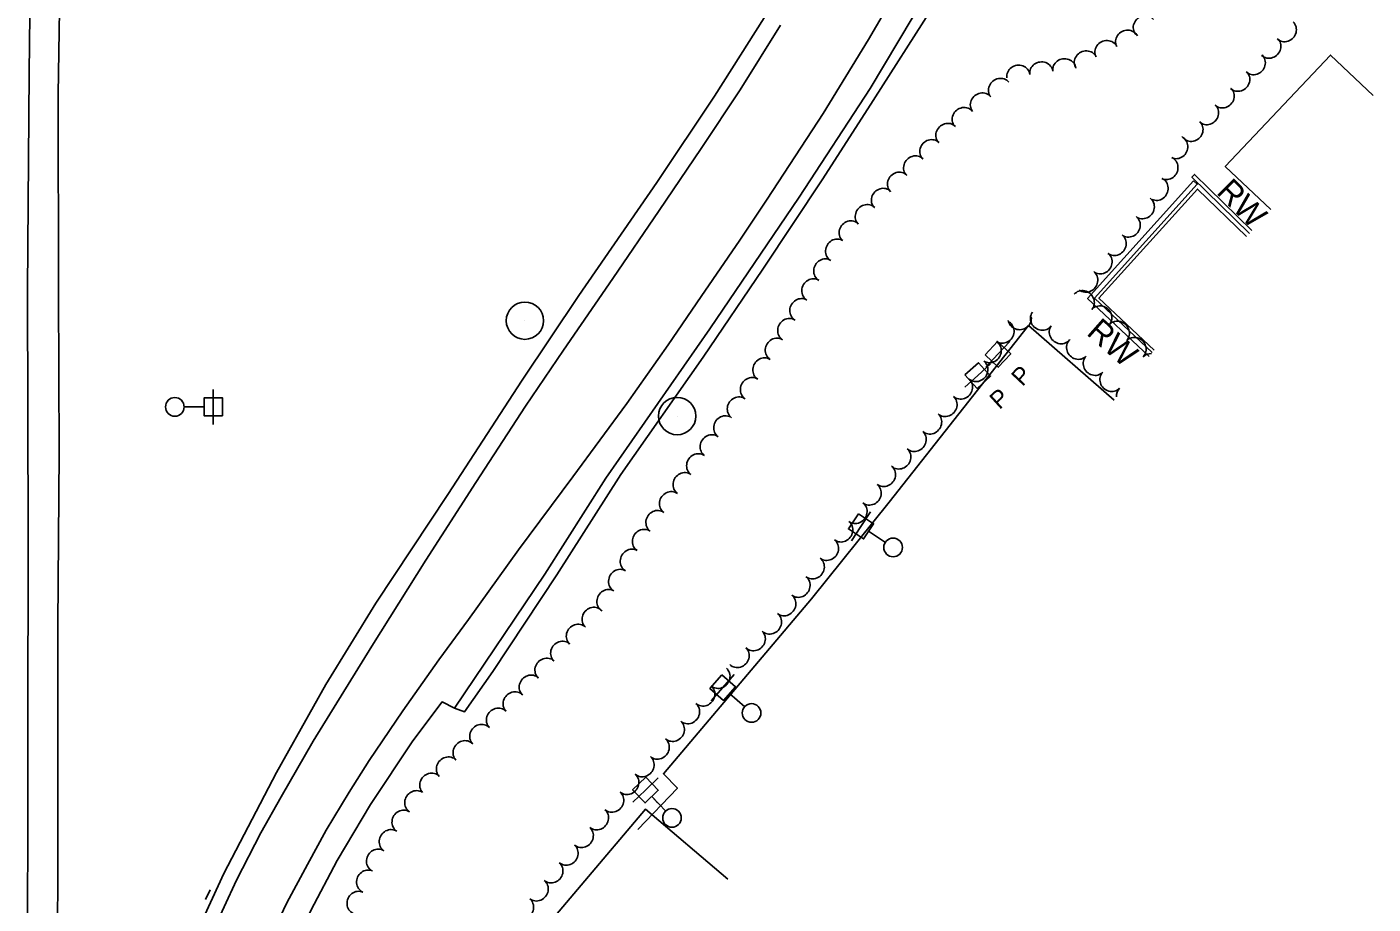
# Model space of a CAD drawing. Extents: x 1746010 to 1754829, y 655801 to 663091.
# Drawn here: x 1754031 to 1754609, y 656182 to 656558 of the extents above; entities that cross this region are included whole.
import ezdxf

# ---------------------------------------------------------------- set-up
doc = ezdxf.new("R2010")
doc.units = 0
for name, color, linetype in [('SURVEY - AERIAL SURVEY - Photo Control - Points - Elevations', 7, 'Continuous'), ('SURVEY - AERIAL SURVEY - Photo Control - Points - Locators', 7, 'Continuous'), ('SURVEY - AERIAL SURVEY - Photo Control - Points - Numbers', 7, 'Continuous'), ('SURVEY - AERIAL SURVEY - Photo Control with Text', 7, 'Continuous'), ('SURVEY - CENTERLINE - Existing Roads - Development', 7, 'Continuous'), ('SURVEY - CENTERLINE - Existing Roads Curve Text', 7, 'Continuous'), ('SURVEY - CENTERLINE - Existing Roads Text', 7, 'Continuous'), ('SURVEY - CONTROL - Points - Elevations', 7, 'Continuous')]:
    doc.layers.add(name, color=color, linetype=linetype)

msp = doc.modelspace()

# ---------------------------------------------------------------- linework, layer by layer
at = {"layer": 'SURVEY - AERIAL SURVEY - Photo Control - Points - Elevations'}
msp.add_lwpolyline([(1754419.31, 656565.92), (1754394.35, 656526.67), (1754372.69, 656493.03), (1754346.92, 656454.31), (1754321.41, 656416.58), (1754286.07, 656366.24), (1754258.62, 656323.18), (1754231.06, 656281.73), (1754218.93, 656264.41), (1754214.58, 656266.09)], dxfattribs=at)
at = {"layer": 'SURVEY - AERIAL SURVEY - Photo Control - Points - Locators'}
for points in [[(1754031.14, 655808.13), (1754031.3, 655908.75), (1754031.72, 656028.9), (1754031.37, 656137), (1754031.54, 656254.42), (1754031.6, 656339.87), (1754031.41, 656445.55), (1754032.12, 656538.49), (1754033.45, 656650.9), (1754034.71, 656754.09), (1754036.08, 656842.73), (1754037.13, 656950.3), (1754039.4, 657051.48), (1754040.61, 657114.04)], [(1754135.7, 656167.8), (1754142.66, 656182.53), (1754151.49, 656198.94), (1754159.61, 656213.69), (1754169.38, 656230.05), (1754178.09, 656243.64), (1754192.43, 656264.92), (1754207.93, 656286.8), (1754220.64, 656304.13), (1754242.16, 656334.02), (1754265.51, 656365.22), (1754288.68, 656396.73), (1754306.3, 656421.85), (1754320.51, 656442.64), (1754337.16, 656466.85), (1754348.88, 656484.44), (1754372.95, 656521.15), (1754392.35, 656552.82), (1754412.99, 656588.12)], [(1754084.44, 655809.57), (1754084.69, 655831.24), (1754087.87, 655887.11), (1754090.59, 655931.61), (1754092.85, 655965.91), (1754095.39, 656000.03), (1754097.87, 656017.46), (1754103.81, 656043.12), (1754111.86, 656075.57), (1754124.11, 656112.66), (1754139.69, 656150.67), (1754153.01, 656179.28), (1754164.3, 656200.66), (1754178.54, 656224.76), (1754196.83, 656252.06), (1754209.33, 656268.76), (1754214.58, 656266.09), (1754253.38, 656323.49), (1754279.59, 656364.66), (1754324.29, 656428.69), (1754362.56, 656485.28), (1754393.05, 656531.8), (1754423.33, 656582.73)], [(1754042.35, 655829.08), (1754043.82, 655829.09), (1754045.64, 655850.26), (1754049.31, 655912.79), (1754052.69, 655977.27), (1754057.4, 656021.81), (1754060.73, 656045.88), (1754064.95, 656065.66), (1754071.74, 656091.74), (1754079.59, 656114.39), (1754096.87, 656154.39), (1754115.64, 656195.17), (1754138.21, 656238.51), (1754159.39, 656276.15), (1754180.9, 656311.04), (1754211.84, 656357.64), (1754243.66, 656406.77), (1754268.05, 656443.08), (1754301.54, 656491.51), (1754326.24, 656528.59), (1754355.07, 656574.05)], [(1754354.57, 656559.06), (1754337.28, 656531.22), (1754320.47, 656506.16), (1754302.46, 656479.56), (1754282.54, 656450.36), (1754261.42, 656419.62), (1754245.09, 656395.59), (1754223.81, 656362.84), (1754202.31, 656329.46), (1754179.19, 656292.71), (1754153.99, 656251.91), (1754140.29, 656228.08), (1754131.51, 656212.62), (1754121.05, 656192.26), (1754110.53, 656169.44)], [(1754554.56, 656468.29), (1754533.61, 656488.71), (1754491.25, 656441.86), (1754515, 656419.62)], [(1754293.32, 656214.06), (1754310.31, 656231.68), (1754304.31, 656237.94), (1754367.83, 656312.9), (1754401.23, 656354.35), (1754461.04, 656430.18), (1754497.71, 656398.19)]]:
    msp.add_lwpolyline(points, dxfattribs=at)
at = {"layer": 'SURVEY - AERIAL SURVEY - Photo Control - Points - Numbers'}
for points in [[(1754052.19, 657082.1), (1754050.4, 657016.97), (1754050.41, 656933.95), (1754048.92, 656857.56), (1754047.62, 656769.57), (1754047.63, 656692.19), (1754047.02, 656648.26), (1754045.2, 656574.61), (1754044.51, 656529.38), (1754044.63, 656444.15), (1754044.94, 656375.53), (1754044.42, 656301.79), (1754044.34, 656224.86), (1754044.22, 656141.35), (1754043.78, 656087.01), (1754044.06, 656016.26), (1754043.35, 655955.88), (1754042, 655902.52), (1754042.42, 655813.6), (1754042.39, 655808.41)], [(1754109.81, 656188.15), (1754107.71, 656183.95)]]:
    msp.add_lwpolyline(points, dxfattribs=at)
at = {"layer": 'SURVEY - AERIAL SURVEY - Photo Control with Text'}
for p, q in [((1754244.87, 656432.23), (1754244.87, 656432.23)), ((1754310.22, 656391.33), (1754310.22, 656391.33))]:
    msp.add_line(p, q, dxfattribs=at)
for centre in [(1754244.87, 656432.23), (1754310.22, 656391.33)]:
    msp.add_circle(centre, 8, dxfattribs=at)
at = {"layer": 'SURVEY - CENTERLINE - Existing Roads - Development'}
for points in [[(1754608.9, 656528.88), (1754590.63, 656546.18), (1754545.44, 656498.45), (1754565, 656479.93)], [(1754556.86, 656470.86), (1754532.26, 656494.97), (1754531.14, 656493.83), (1754555.8, 656469.68)], [(1754531.82, 656492.24), (1754486.34, 656441.83), (1754512.8, 656416.9)], [(1754531.82, 656492.24), (1754533.42, 656490.78), (1754489.35, 656441.94), (1754514.15, 656418.57)], [(1754331.96, 656192.68), (1754296.57, 656222.69), (1754241.36, 656157.56), (1754238.62, 656159.89), (1754218, 656135.57), (1754220.55, 656133.4), (1754165.06, 656067.95), (1754215.07, 656025.56), (1754221.68, 656033.36)]]:
    msp.add_lwpolyline(points, dxfattribs=at)
at = {"layer": 'SURVEY - CENTERLINE - Existing Roads Curve Text'}
for p, q in [((1754447.89, 656417.82), (1754453.02, 656423.29)), ((1754447.89, 656417.82), (1754442.75, 656412.35)), ((1754439.21, 656408.74), (1754433.66, 656403.7)), ((1754439.21, 656408.74), (1754444.77, 656413.77)), ((1754111.11, 656395.28), (1754111.1, 656402.79)), ((1754098.51, 656395.27), (1754107.21, 656395.28)), ((1754106.81, 656395.28), (1754103.61, 656395.28)), ((1754111.11, 656395.28), (1754111.12, 656387.78)), ((1754389.1, 656344.04), (1754393.22, 656350.31)), ((1754389.1, 656344.04), (1754384.99, 656337.76)), ((1754399.64, 656337.13), (1754392.36, 656341.9)), ((1754392.7, 656341.68), (1754395.38, 656339.92)), ((1754329.78, 656274.88), (1754334.73, 656280.51)), ((1754329.78, 656274.88), (1754324.82, 656269.26)), ((1754339.23, 656266.56), (1754332.7, 656272.31)), ((1754333, 656272.04), (1754335.41, 656269.93)), ((1754296.62, 656230.94), (1754302.05, 656236.11)), ((1754296.62, 656230.94), (1754291.19, 656225.77)), ((1754305.31, 656221.82), (1754299.31, 656228.11)), ((1754299.58, 656227.83), (1754301.79, 656225.51))]:
    msp.add_line(p, q, dxfattribs=at)
for points in [[(1754442.38, 656417.65), (1754447.72, 656423.33), (1754453.4, 656417.99), (1754448.06, 656412.31)], [(1754433.71, 656409.01), (1754439.48, 656414.24), (1754444.72, 656408.47), (1754438.94, 656403.23)], [(1754115.02, 656391.39), (1754107.22, 656391.38), (1754107.21, 656399.18), (1754115.01, 656399.19)], [(1754387.98, 656349.44), (1754394.5, 656345.16), (1754390.23, 656338.64), (1754383.7, 656342.91)], [(1754329.43, 656280.39), (1754335.28, 656275.23), (1754330.12, 656269.38), (1754324.27, 656274.53)], [(1754296.75, 656236.45), (1754302.13, 656230.81), (1754296.48, 656225.43), (1754291.1, 656231.07)]]:
    msp.add_lwpolyline(points, close=True, dxfattribs=at)
for centre in [(1754094.61, 656395.27), (1754402.9, 656334.99), (1754342.16, 656263.98), (1754308, 656218.99)]:
    msp.add_circle(centre, 4, dxfattribs=at)
at = {"layer": 'SURVEY - CENTERLINE - Existing Roads Text'}
for centre, major_axis, start_param, end_param in [((1754510.84, 656558.25), (3.82, 3.22), 0, 3.141593), ((1754571.16, 656556.76), (-3.42, -3.64), 0, 3.141593), ((1754494.45, 656547.65), (4.47, 2.25), 0, 3.141593), ((1754503.3, 656552.11), (4.47, 2.25), 0, 3.141593), ((1754564.49, 656549.67), (-3.42, -3.64), 0, 3.141593), ((1754485.61, 656543.2), (4.47, 2.25), 0, 3.141593), ((1754456.69, 656537.15), (4.95, 0.7), 0, 3.141593), ((1754466.54, 656538.54), (4.95, 0.7), 0, 3.141593), ((1754476.38, 656539.92), (4.95, 0.7), 0, 3.141593), ((1754557.83, 656542.57), (-3.42, -3.64), 0, 3.141593), ((1754448.71, 656531.37), (3.9, 3.13), 0, 3.141593), ((1754551.16, 656535.48), (-3.42, -3.64), 0, 3.141593), ((1754440.92, 656525.13), (3.9, 3.13), 0, 3.141593), ((1754544.47, 656528.33), (-3.41, -3.65), 0, 3.141593), ((1754433.14, 656518.89), (3.9, 3.13), 0, 3.141593), ((1754537.78, 656521.17), (-3.41, -3.65), 0, 3.141593), ((1754426.09, 656512.03), (3.52, 3.55), 0, 3.141593), ((1754531.09, 656514), (-3.41, -3.65), 0, 3.141593), ((1754419.17, 656505.06), (3.52, 3.55), 0, 3.141593), ((1754524.64, 656506.66), (-2.13, -4.52), 0, 3.141593), ((1754412.25, 656498.1), (3.52, 3.55), 0, 3.141593), ((1754520.42, 656497.71), (-2.13, -4.52), 0, 3.141593), ((1754405.33, 656491.13), (3.52, 3.55), 0, 3.141593), ((1754398.41, 656484.17), (3.52, 3.55), 0, 3.141593), ((1754516.2, 656488.76), (-2.13, -4.52), 0, 3.141593), ((1754510.22, 656480.86), (-3.04, -3.97), 0, 3.141593), ((1754391.49, 656477.2), (3.52, 3.55), 0, 3.141593), ((1754384.57, 656470.24), (3.52, 3.55), 0, 3.141593), ((1754504.19, 656472.98), (-3.04, -3.97), 0, 3.141593), ((1754378.72, 656462.35), (2.58, 4.29), 0, 3.141593), ((1754498.16, 656465.1), (-3.04, -3.97), 0, 3.141593), ((1754492.09, 656457.22), (-3.08, -3.94), 0, 3.141593), ((1754373.6, 656453.83), (2.58, 4.29), 0, 3.141593), ((1754368.48, 656445.31), (2.58, 4.29), 0, 3.141593), ((1754485.94, 656449.35), (-3.08, -3.94), 0, 3.141593), ((1754484.4, 656440.32), (3.78, -3.27), 0, 3.141593), ((1754363.35, 656436.8), (2.58, 4.29), 0, 3.141593), ((1754491.96, 656433.79), (3.78, -3.27), 0, 3.141593), ((1754358.15, 656428.3), (2.67, 4.23), 0, 3.141593), ((1754450.02, 656427.48), (-2.74, -4.18), 0, 3.141593), ((1754457.26, 656433.1), (-4.95, -0.73), 0, 3.141593), ((1754466.74, 656432.94), (-4.06, 2.92), 0, 3.141593), ((1754499.47, 656427.18), (3.6, -3.47), 0, 3.141593), ((1754352.81, 656419.85), (2.67, 4.23), 0, 3.141593), ((1754474.79, 656427.13), (-4.06, 2.92), 0, 3.141593), ((1754506.67, 656420.24), (3.6, -3.47), 0, 3.141593), ((1754444.54, 656419.12), (-2.74, -4.18), 0, 3.141593), ((1754482.18, 656420.51), (-3.6, 3.47), 0, 3.141593), ((1754347.47, 656411.4), (2.67, 4.23), 0, 3.141593), ((1754438.76, 656410.98), (-3.31, -3.75), 0, 3.141593), ((1754489.33, 656413.62), (-3.6, 3.47), 0, 3.141593), ((1754513.87, 656413.3), (3.6, -3.47), 2.320778, 3.141593), ((1754342.13, 656402.94), (2.67, 4.23), 0, 3.141593), ((1754496.49, 656406.73), (-3.6, 3.47), 0, 3.141593), ((1754432.15, 656403.48), (-3.31, -3.75), 0, 3.141593), ((1754503.65, 656399.83), (-3.6, 3.47), 0, 0.846007), ((1754336.52, 656394.68), (2.91, 4.06), 0, 3.141593), ((1754425.53, 656395.99), (-3.31, -3.75), 0, 3.141593), ((1754330.7, 656386.56), (2.91, 4.06), 0, 3.141593), ((1754418.92, 656388.49), (-3.31, -3.75), 0, 3.141593), ((1754324.88, 656378.44), (2.91, 4.06), 0, 3.141593), ((1754412.3, 656380.99), (-3.31, -3.75), 0, 3.141593), ((1754319.06, 656370.32), (2.91, 4.06), 0, 3.141593), ((1754405.69, 656373.49), (-3.31, -3.75), 0, 3.141593), ((1754313.24, 656362.2), (2.91, 4.06), 0, 3.141593), ((1754399.12, 656365.96), (-3.06, -3.96), 0, 3.141593), ((1754393.01, 656358.04), (-3.06, -3.96), 0, 3.141593), ((1754307.42, 656354.08), (2.91, 4.06), 0, 3.141593), ((1754301.6, 656345.96), (2.91, 4.06), 0, 3.141593), ((1754386.9, 656350.13), (-3.06, -3.96), 0, 3.141593), ((1754380.79, 656342.21), (-3.06, -3.96), 0, 3.141593), ((1754295.78, 656337.84), (2.91, 4.06), 0, 3.141593), ((1754290.56, 656329.34), (2.51, 4.32), 0, 3.141593), ((1754374.68, 656334.3), (-3.06, -3.96), 0, 3.141593), ((1754368.57, 656326.38), (-3.06, -3.96), 0, 3.141593), ((1754285.55, 656320.7), (2.51, 4.32), 0, 3.141593), ((1754362.46, 656318.47), (-3.06, -3.96), 0, 3.141593), ((1754280.54, 656312.06), (2.51, 4.32), 0, 3.141593), ((1754274.22, 656304.45), (3.4, 3.67), 0, 3.141593), ((1754356.35, 656310.55), (-3.06, -3.96), 0, 3.141593), ((1754350.18, 656302.69), (-3.48, -3.59), 0, 3.141593), ((1754267.48, 656297.18), (3.4, 3.67), 0, 3.141593), ((1754343.24, 656295.5), (-3.48, -3.59), 0, 3.141593), ((1754260.74, 656289.91), (3.4, 3.67), 0, 3.141593), ((1754254, 656282.64), (3.4, 3.67), 0, 3.141593), ((1754336.29, 656288.31), (-3.48, -3.59), 0, 3.141593), ((1754328.08, 656279.4), (-3.26, -3.79), 0, 3.141593), ((1754247.27, 656275.37), (3.4, 3.67), 0, 3.141593), ((1754321.56, 656271.81), (-3.26, -3.79), 0, 3.141593), ((1754240.34, 656268.22), (3.58, 3.49), 0, 3.141593), ((1754233.19, 656261.24), (3.58, 3.49), 0, 3.141593), ((1754315.04, 656264.23), (-3.26, -3.79), 0, 3.141593), ((1754226.03, 656254.26), (3.58, 3.49), 0, 3.141593), ((1754308.52, 656256.64), (-3.26, -3.79), 0, 3.141593), ((1754218.87, 656247.27), (3.58, 3.49), 0, 3.141593), ((1754302.01, 656249.06), (-3.26, -3.79), 0, 3.141593), ((1754211.71, 656240.29), (3.58, 3.49), 0, 3.141593), ((1754295.49, 656241.47), (-3.26, -3.79), 0, 3.141593), ((1754204.56, 656233.31), (3.58, 3.49), 0, 3.141593), ((1754288.97, 656233.89), (-3.26, -3.79), 0, 3.141593), ((1754198.08, 656225.77), (2.74, 4.18), 0, 3.141593), ((1754282.45, 656226.3), (-3.26, -3.79), 0, 3.141593), ((1754192.6, 656217.41), (2.74, 4.18), 0, 3.141593), ((1754275.94, 656218.72), (-3.26, -3.79), 0, 3.141593), ((1754187.13, 656209.05), (2.74, 4.18), 0, 3.141593), ((1754269.42, 656211.13), (-3.26, -3.79), 0, 3.141593), ((1754181.65, 656200.7), (2.74, 4.18), 0, 3.141593), ((1754262.9, 656203.55), (-3.26, -3.79), 0, 3.141593), ((1754177.36, 656191.68), (2.05, 4.56), 0, 3.141593), ((1754256.38, 656195.96), (-3.26, -3.79), 0, 3.141593), ((1754250.07, 656188.21), (-3.15, -3.88), 0, 3.141593), ((1754173.27, 656182.56), (2.05, 4.56), 0, 3.141593), ((1754243.78, 656180.44), (-3.15, -3.88), 0, 3.141593)]:
    msp.add_ellipse(centre, major_axis=major_axis, ratio=0.940188, start_param=start_param, end_param=end_param, dxfattribs=at)

# ---------------------------------------------------------------- texts
at = {"layer": 'SURVEY - CENTERLINE - Existing Roads Curve Text'}
for rotation, p in [(46.80108, (1754458.38, 656403.72)), (42.1926, (1754448.54, 656393.84))]:
    msp.add_text('P', height=7.48, rotation=rotation, dxfattribs=at).set_placement(p)
at = {"layer": 'SURVEY - CONTROL - Points - Elevations'}
for rotation, p in [(314.93183, (1754541.28, 656487.02)), (318.55004, (1754485.5, 656426.55))]:
    msp.add_text('RW', height=10.001, rotation=rotation, dxfattribs=at).set_placement(p)

doc.saveas('drawing.dxf')
